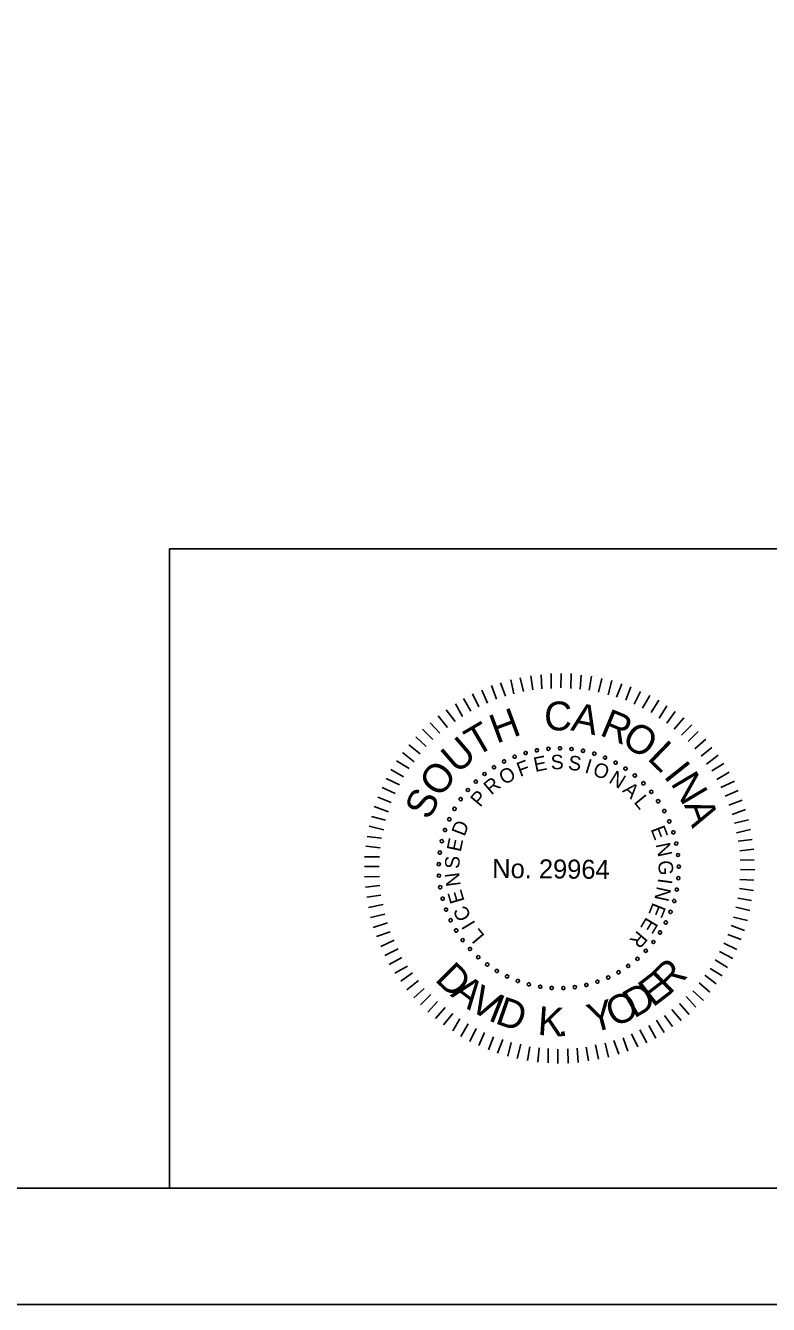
# Model space of a CAD drawing. Extents: x -133.1 to -97, y -1.7 to 20.3.
# Drawn here: x -111.12 to -107.93, y -1.69 to 3.81 of the extents above; entities that cross this region are included whole.
import ezdxf

# ---------------------------------------------------------------- set-up
doc = ezdxf.new("R2010")
doc.units = 0
for name, color, linetype in [('BR_BORDER LINES', 7, 'Continuous'), ('BR_TEXT', 7, 'Continuous'), ('Level 31', 7, 'Continuous')]:
    doc.layers.add(name, color=color, linetype=linetype)

msp = doc.modelspace()

# ---------------------------------------------------------------- linework, layer by layer
at = {"layer": 'BR_BORDER LINES'}
for p, q in [((-110.5071, 1.5591), (-105.1419, 1.5591)), ((-110.5071, -1.191), (-110.5071, 1.5591)), ((-131.3076, -1.191), (-97.6416, -1.191))]:
    msp.add_line(p, q, dxfattribs=at)
at = {"layer": 'BR_TEXT'}
for p, q in [((-109.0262, 0.9348), (-109.0394, 0.9958)), ((-108.9849, 0.9447), (-108.999, 1.0041)), ((-108.9454, 0.9521), (-108.9543, 1.0131)), ((-108.9059, 0.9561), (-108.9097, 1.017)), ((-108.8664, 0.9584), (-108.8658, 1.0227)), ((-108.8243, 0.9606), (-108.8238, 1.0224)), ((-108.7823, 0.9577), (-108.78, 1.022)), ((-108.742, 0.9548), (-108.7372, 1.0156)), ((-108.7034, 0.9501), (-108.6926, 1.011)), ((-108.6631, 0.9421), (-108.6489, 1.0012)), ((-108.622, 0.9314), (-108.606, 0.9922)), ((-109.1406, 0.8954), (-109.1642, 0.9514)), ((-109.1019, 0.9122), (-109.1229, 0.9708)), ((-109.0623, 0.9248), (-109.0842, 0.9824)), ((-108.5852, 0.9208), (-108.5633, 0.9781)), ((-108.5458, 0.9076), (-108.5239, 0.9658)), ((-108.5099, 0.8902), (-108.482, 0.9457)), ((-109.2475, 0.8371), (-109.278, 0.8914)), ((-109.2122, 0.8608), (-109.2426, 0.9151)), ((-109.1777, 0.8785), (-109.2039, 0.9345)), ((-108.474, 0.8727), (-108.4427, 0.9282)), ((-108.4364, 0.8544), (-108.4042, 0.9082)), ((-108.4031, 0.8301), (-108.3692, 0.8839)), ((-109.3123, 0.7904), (-109.3522, 0.8405)), ((-109.2786, 0.8159), (-109.3177, 0.8668)), ((-108.3699, 0.8083), (-108.3334, 0.8587)), ((-108.3375, 0.7824), (-108.2968, 0.8318)), ((-109.3745, 0.7386), (-109.4188, 0.7827)), ((-109.3451, 0.7658), (-109.3868, 0.8107)), ((-108.3059, 0.7572), (-108.2627, 0.8014)), ((-108.2779, 0.7295), (-108.2346, 0.7729)), ((-109.4291, 0.6763), (-109.4786, 0.7154)), ((-109.4039, 0.7079), (-109.4474, 0.7503)), ((-108.2498, 0.6984), (-108.2022, 0.74)), ((-109.4551, 0.6431), (-109.5046, 0.683)), ((-108.2226, 0.6664), (-108.1759, 0.7046)), ((-108.1988, 0.6327), (-108.1496, 0.6718)), ((-109.5012, 0.5774), (-109.5549, 0.6096)), ((-109.4768, 0.6141), (-109.5306, 0.6472)), ((-108.1768, 0.6034), (-108.1242, 0.6355)), ((-109.5186, 0.5432), (-109.575, 0.5711)), ((-108.1548, 0.5663), (-108.1013, 0.5976)), ((-108.137, 0.5318), (-108.0793, 0.5588)), ((-109.5361, 0.5065), (-109.5933, 0.5318)), ((-108.1193, 0.4948), (-108.0624, 0.5192)), ((-109.5659, 0.4278), (-109.6275, 0.4506)), ((-109.5536, 0.468), (-109.6117, 0.4899)), ((-108.1025, 0.456), (-108.0456, 0.477)), ((-109.5782, 0.3918), (-109.639, 0.4069)), ((-108.0891, 0.4156), (-108.0314, 0.4374)), ((-108.079, 0.3794), (-108.0189, 0.3935)), ((-109.5854, 0.3498), (-109.6479, 0.3658)), ((-108.0708, 0.3373), (-108.0106, 0.3522)), ((-109.6006, 0.2727), (-109.6624, 0.2801)), ((-109.596, 0.3138), (-109.6569, 0.3221)), ((-108.0625, 0.3012), (-108.0033, 0.3084)), ((-109.6035, 0.2333), (-109.6679, 0.2338)), ((-108.056, 0.26), (-107.995, 0.2663)), ((-108.0546, 0.2205), (-107.9945, 0.22)), ((-109.6056, 0.1921), (-109.6682, 0.1926)), ((-108.0524, 0.1793), (-107.9915, 0.1788)), ((-109.6042, 0.1492), (-109.6686, 0.148)), ((-109.602, 0.1105), (-109.6638, 0.1033)), ((-108.0553, 0.1364), (-107.9952, 0.1342)), ((-109.598, 0.0693), (-109.659, 0.0604)), ((-108.0645, 0.0566), (-108.0054, 0.0467)), ((-108.0574, 0.0978), (-107.9965, 0.0896)), ((-109.5881, 0.0297), (-109.6508, 0.0165)), ((-108.0735, 0.0172), (-108.0135, 0.003)), ((-109.5815, -0.0124), (-109.6426, -0.0265)), ((-109.5698, -0.0493), (-109.6318, -0.0703)), ((-108.0824, -0.0248), (-108.0224, -0.0398)), ((-109.5582, -0.0881), (-109.6167, -0.1091)), ((-108.107, -0.1001), (-108.0506, -0.122)), ((-108.093, -0.0615), (-108.0357, -0.0835)), ((-109.5413, -0.1251), (-109.599, -0.1521)), ((-109.5244, -0.1613), (-109.5813, -0.1909)), ((-108.1245, -0.1368), (-108.0681, -0.1647)), ((-109.5076, -0.1984), (-109.5619, -0.2297)), ((-108.1612, -0.2095), (-108.1082, -0.2417)), ((-108.1428, -0.1727), (-108.0856, -0.2032)), ((-109.4838, -0.2355), (-109.5382, -0.2668)), ((-109.4626, -0.2648), (-109.5127, -0.3013)), ((-108.1838, -0.2462), (-108.1317, -0.2784)), ((-109.4372, -0.2985), (-109.4873, -0.3376)), ((-108.2306, -0.3084), (-108.1846, -0.3483)), ((-108.2063, -0.2752), (-108.1577, -0.3125)), ((-109.4125, -0.3321), (-109.4567, -0.373)), ((-109.3836, -0.3582), (-109.4286, -0.4032)), ((-108.2869, -0.3672), (-108.2444, -0.413)), ((-108.2583, -0.3417), (-108.2115, -0.3833)), ((-109.3547, -0.3884), (-109.3971, -0.4344)), ((-109.3222, -0.4144), (-109.363, -0.4613)), ((-108.3474, -0.4225), (-108.3075, -0.47)), ((-108.3155, -0.397), (-108.273, -0.4437)), ((-109.289, -0.4404), (-109.3289, -0.4882)), ((-109.2583, -0.4622), (-109.2896, -0.5142)), ((-109.2233, -0.4847), (-109.2546, -0.5386)), ((-108.4475, -0.4911), (-108.4162, -0.5455)), ((-108.4139, -0.4691), (-108.3808, -0.5217)), ((-108.3802, -0.448), (-108.3446, -0.4963)), ((-109.1891, -0.5048), (-109.2162, -0.5603)), ((-109.1523, -0.5222), (-109.1769, -0.5778)), ((-109.1139, -0.5397), (-109.1358, -0.5962)), ((-108.5578, -0.5443), (-108.5368, -0.6011)), ((-108.5216, -0.5274), (-108.4947, -0.5835)), ((-108.4855, -0.5106), (-108.455, -0.5666)), ((-109.0745, -0.552), (-109.0973, -0.6102)), ((-109.0386, -0.5644), (-109.0528, -0.6235)), ((-108.9974, -0.5716), (-109.0126, -0.6333)), ((-108.9581, -0.5831), (-108.968, -0.6413)), ((-108.9186, -0.5877), (-108.9234, -0.6494)), ((-108.8792, -0.5906), (-108.8797, -0.6524)), ((-108.8372, -0.5935), (-108.8377, -0.6544)), ((-108.7951, -0.5913), (-108.7939, -0.6531)), ((-108.7547, -0.589), (-108.7509, -0.6509)), ((-108.7161, -0.5851), (-108.7062, -0.6435)), ((-108.6756, -0.5742), (-108.6624, -0.6361)), ((-108.6344, -0.5677), (-108.6194, -0.627)), ((-108.5974, -0.556), (-108.5764, -0.6145))]:
    msp.add_line(p, q, dxfattribs=at)
for centre, start, end in [((-109.0235, 0.6646), 21.6807, 201.6807), ((-109.0235, 0.6646), 201.6807, 21.6807), ((-108.9763, 0.6806), 16.1422, 196.1422), ((-108.9763, 0.6806), 196.1422, 16.1422), ((-108.9278, 0.692), 10.6038, 190.6038), ((-108.9278, 0.692), 190.6038, 10.6038), ((-108.8784, 0.6987), 5.0653, 185.0653), ((-108.8784, 0.6987), 185.0653, 5.0653), ((-108.8286, 0.7006), 359.5268, 179.5268), ((-108.8286, 0.7006), 179.5268, 359.5268), ((-108.7789, 0.6977), 173.9884, 353.9884), ((-108.7789, 0.6977), 353.9884, 173.9884), ((-108.7296, 0.69), 168.4499, 348.4499), ((-108.7296, 0.69), 348.4499, 168.4499), ((-108.6814, 0.6776), 162.9114, 342.9114), ((-108.6814, 0.6776), 342.9114, 162.9114), ((-108.6345, 0.6606), 157.373, 337.373), ((-108.6345, 0.6606), 337.373, 157.373), ((-109.1121, 0.6192), 32.7576, 212.7576), ((-109.1121, 0.6192), 212.7576, 32.7576), ((-109.0689, 0.644), 27.2191, 207.2191), ((-109.0689, 0.644), 207.2191, 27.2191), ((-108.5896, 0.6391), 151.8345, 331.8345), ((-108.5896, 0.6391), 331.8345, 151.8345), ((-108.5469, 0.6134), 146.2961, 326.2961), ((-108.5469, 0.6134), 326.2961, 146.2961), ((-109.1903, 0.5577), 43.8345, 223.8345), ((-109.1903, 0.5577), 223.8345, 43.8345), ((-109.1527, 0.5903), 38.2961, 218.2961), ((-109.1527, 0.5903), 218.2961, 38.2961), ((-108.5069, 0.5837), 140.7576, 320.7576), ((-108.5069, 0.5837), 320.7576, 140.7576), ((-108.4699, 0.5503), 135.2191, 315.2191), ((-108.4699, 0.5503), 315.2191, 135.2191), ((-109.2246, 0.5215), 49.373, 229.373), ((-109.2246, 0.5215), 229.373, 49.373), ((-108.4363, 0.5134), 129.6807, 309.6807), ((-108.4363, 0.5134), 309.6807, 129.6807), ((-109.282, 0.4402), 60.4499, 240.4499), ((-109.282, 0.4402), 240.4499, 60.4499), ((-109.2553, 0.4822), 54.9114, 234.9114), ((-109.2553, 0.4822), 234.9114, 54.9114), ((-108.4065, 0.4735), 124.1422, 304.1422), ((-108.4065, 0.4735), 304.1422, 124.1422), ((-109.3045, 0.3957), 65.9884, 245.9884), ((-109.3045, 0.3957), 245.9884, 65.9884), ((-108.3806, 0.4309), 118.6038, 298.6038), ((-108.3806, 0.4309), 298.6038, 118.6038), ((-108.359, 0.3861), 113.0653, 293.0653), ((-108.359, 0.3861), 293.0653, 113.0653), ((-109.3227, 0.3493), 71.5268, 251.5268), ((-109.3227, 0.3493), 251.5268, 71.5268), ((-108.3418, 0.3393), 107.5268, 287.5268), ((-108.3418, 0.3393), 287.5268, 107.5268), ((-109.3363, 0.3014), 77.0653, 257.0653), ((-109.3363, 0.3014), 257.0653, 77.0653), ((-108.3292, 0.2911), 101.9884, 281.9884), ((-108.3292, 0.2911), 281.9884, 101.9884), ((-109.3452, 0.2524), 82.6038, 262.6038), ((-109.3452, 0.2524), 262.6038, 82.6038), ((-108.3213, 0.2419), 96.4499, 276.4499), ((-108.3213, 0.2419), 276.4499, 96.4499), ((-109.3493, 0.2027), 88.1422, 268.1422), ((-109.3493, 0.2027), 268.1422, 88.1422), ((-108.3182, 0.1921), 90.9114, 270.9114), ((-108.3182, 0.1921), 270.9114, 90.9114), ((-109.3486, 0.1529), 93.6807, 273.6807), ((-109.3431, 0.1033), 99.2191, 279.2191), ((-109.3486, 0.1529), 273.6807, 93.6807), ((-109.3431, 0.1033), 279.2191, 99.2191), ((-108.3199, 0.1423), 85.373, 265.373), ((-108.3199, 0.1423), 265.373, 85.373), ((-109.3328, 0.0546), 104.7576, 284.7576), ((-109.3328, 0.0546), 284.7576, 104.7576), ((-108.3265, 0.0929), 79.8345, 259.8345), ((-108.3265, 0.0929), 259.8345, 79.8345), ((-109.3179, 0.007), 110.2961, 290.2961), ((-109.3179, 0.007), 290.2961, 110.2961), ((-108.3536, -0.0028), 68.7576, 248.7576), ((-108.3536, -0.0028), 248.7576, 68.7576), ((-108.3377, 0.0444), 74.2961, 254.2961), ((-108.3377, 0.0444), 254.2961, 74.2961), ((-109.2985, -0.0389), 115.8345, 295.8345), ((-109.2985, -0.0389), 295.8345, 115.8345), ((-108.374, -0.0483), 63.2191, 243.2191), ((-108.374, -0.0483), 243.2191, 63.2191), ((-109.2747, -0.0826), 121.373, 301.373), ((-109.2747, -0.0826), 301.373, 121.373), ((-108.3986, -0.0916), 57.6807, 237.6807), ((-108.3986, -0.0916), 237.6807, 57.6807), ((-109.2468, -0.1239), 126.9114, 306.9114), ((-109.2468, -0.1239), 306.9114, 126.9114), ((-109.2151, -0.1624), 132.4499, 312.4499), ((-109.2151, -0.1624), 312.4499, 132.4499), ((-108.4599, -0.1701), 46.6038, 226.6038), ((-108.4273, -0.1323), 52.1422, 232.1422), ((-108.4273, -0.1323), 232.1422, 52.1422), ((-109.1798, -0.1975), 137.9884, 317.9884), ((-109.1798, -0.1975), 317.9884, 137.9884), ((-108.4959, -0.2045), 41.0653, 221.0653), ((-108.4959, -0.2045), 221.0653, 41.0653), ((-108.4599, -0.1701), 226.6038, 46.6038), ((-109.1413, -0.2291), 143.5268, 323.5268), ((-109.1413, -0.2291), 323.5268, 143.5268), ((-109.0999, -0.2569), 149.0653, 329.0653), ((-109.0999, -0.2569), 329.0653, 149.0653), ((-109.056, -0.2805), 334.6038, 154.6038), ((-108.577, -0.2622), 29.9884, 209.9884), ((-108.577, -0.2622), 209.9884, 29.9884), ((-108.5351, -0.2353), 35.5268, 215.5268), ((-108.5351, -0.2353), 215.5268, 35.5268), ((-109.056, -0.2805), 154.6038, 334.6038), ((-109.01, -0.2997), 160.1422, 340.1422), ((-109.01, -0.2997), 340.1422, 160.1422), ((-108.9624, -0.3145), 165.6807, 345.6807), ((-108.9624, -0.3145), 345.6807, 165.6807), ((-108.9136, -0.3245), 171.2191, 351.2191), ((-108.9136, -0.3245), 351.2191, 171.2191), ((-108.8641, -0.3299), 356.7576, 176.7576), ((-108.8641, -0.3299), 176.7576, 356.7576), ((-108.8142, -0.3304), 2.2961, 182.2961), ((-108.7646, -0.3261), 7.8345, 187.8345), ((-108.7646, -0.3261), 187.8345, 7.8345), ((-108.7156, -0.317), 13.373, 193.373), ((-108.7156, -0.317), 193.373, 13.373), ((-108.6677, -0.3032), 18.9114, 198.9114), ((-108.6677, -0.3032), 198.9114, 18.9114), ((-108.6214, -0.2849), 24.4499, 204.4499), ((-108.6214, -0.2849), 204.4499, 24.4499), ((-108.8142, -0.3304), 182.2961, 2.2961)]:
    msp.add_arc(centre, 0.00701, start, end, dxfattribs=at)
at = {"layer": 'Level 31'}
msp.add_lwpolyline([(-133.1409, -1.691), (-97.141, -1.691), (-97.141, 20.309), (-133.1409, 20.309)], close=True, dxfattribs=at)

# ---------------------------------------------------------------- texts
at = {"layer": 'BR_TEXT'}
for s, height, rotation, p in [('C', 0.1241, 359.5482, (-108.8971, 0.7782)), ('A', 0.1241, 348.1981, (-108.7857, 0.779)), ('H', 0.1241, 20.3637, (-109.1015, 0.7199)), ('R', 0.1241, 337.4344, (-108.6624, 0.7591)), ('T', 0.1241, 30.4992, (-109.1894, 0.6624)), ('O', 0.1239, 326.5869, (-108.5702, 0.7224)), ('U', 0.1241, 40.8022, (-109.2706, 0.5876)), ('L', 0.1241, 315.9488, (-108.4576, 0.6546)), ('E', 0.0622, 11.4103, (-108.9351, 0.5987)), ('S', 0.0622, 2.208, (-108.8672, 0.6097)), ('S', 0.0622, 352.6608, (-108.796, 0.6095)), ('O', 0.1241, 52.0267, (-109.3451, 0.4837)), ('O', 0.0622, 30.8477, (-109.0676, 0.541)), ('F', 0.0622, 20.6127, (-109.0002, 0.577)), ('I', 0.0622, 343.1136, (-108.7257, 0.5975)), ('O', 0.0622, 338.4392, (-108.6923, 0.5873)), ('N', 0.0622, 328.2042, (-108.6227, 0.5559)), ('I', 0.1241, 308.6613, (-108.3862, 0.5803)), ('R', 0.0622, 40.3949, (-109.1237, 0.4971)), ('N', 0.1241, 300.7037, (-108.3556, 0.5509)), ('S', 0.1239, 63.2511, (-109.3905, 0.3881)), ('P', 0.0622, 49.9421, (-109.1718, 0.4445)), ('A', 0.0622, 318.657, (-108.5637, 0.5159)), ('L', 0.0622, 309.4546, (-108.5139, 0.4686)), ('A', 0.1241, 289.4792, (-108.2964, 0.4579)), ('D', 0.0622, 69.0364, (-109.2388, 0.3192)), ('E', 0.0622, 291.049, (-108.44, 0.3533)), ('E', 0.0622, 78.2388, (-109.2553, 0.2526)), ('N', 0.0622, 281.8466, (-108.4179, 0.2882)), ('S', 0.0622, 87.786, (-109.2611, 0.1815)), ('No. 29964', 0.08175, 359.5268, (-109.1199, 0.1431)), ('G', 0.0622, 272.2995, (-108.4061, 0.2179)), ('N', 0.0622, 97.3332, (-109.2549, 0.1105)), ('I', 0.0622, 262.4084, (-108.4065, 0.1441)), ('E', 0.0622, 106.5355, (-109.2379, 0.044)), ('N', 0.0622, 257.7339, (-108.411, 0.1095)), ('C', 0.0622, 116.4266, (-109.208, -0.0235)), ('E', 0.0622, 248.1867, (-108.4291, 0.0406)), ('I', 0.0622, 121.1011, (-109.1899, -0.0534)), ('E', 0.0622, 238.9844, (-108.457, -0.0222)), ('L', 0.0622, 129.9595, (-109.1493, -0.1056)), ('R', 0.0622, 229.782, (-108.4947, -0.0797)), ('D', 0.1236, 315.4053, (-109.3698, -0.2962)), ('R', 0.1236, 44.5947, (-108.3589, -0.3617)), ('E', 0.1236, 37.5339, (-108.4295, -0.4156)), ('A', 0.1236, 322.8377, (-109.3032, -0.3618)), ('V', 0.1236, 330.5179, (-109.226, -0.42)), ('D', 0.1236, 30.1015, (-108.5104, -0.4626)), ('I', 0.1236, 338.1981, (-109.1418, -0.4674)), ('D', 0.1236, 340.7995, (-109.1119, -0.4808)), ('Y', 0.1236, 14.8649, (-108.6915, -0.5241)), ('O', 0.1236, 22.4212, (-108.5997, -0.4996)), ('K', 0.1236, 356.098, (-108.9267, -0.5314)), ('.', 0.1236, 3.1588, (-108.838, -0.5377))]:
    msp.add_text(s, height=height, rotation=rotation, dxfattribs=at).set_placement(p)

doc.saveas('drawing.dxf')
